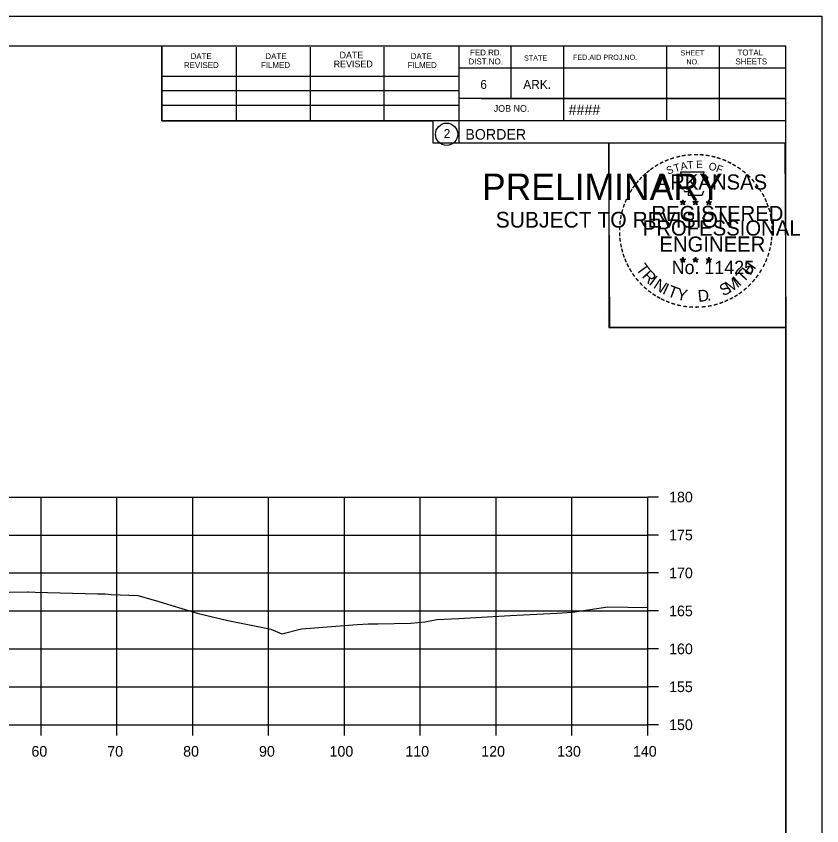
# Model space of a CAD drawing. Extents: x 1368503 to 1373085, y 379840 to 381833.
# Drawn here: x 1372978.8 to 1373085, y 381135 to 381241.7 of the extents above; entities that cross this region are included whole.
import ezdxf

# ---------------------------------------------------------------- set-up
doc = ezdxf.new("R2010")
doc.units = 0
for name, color, linetype in [('S_BRIDGE', 7, 'Continuous'), ('S_EDGE_PAVEMENT', 7, 'Continuous'), ('S_LANDSCAPING', 7, 'Continuous'), ('S_MISC_BOUNDARY', 7, 'Continuous'), ('S_MISC_BOUNDARY_ANNOT', 7, 'Continuous'), ('S_PHOTO_CENTERS', 7, 'Continuous'), ('S_PHOTO_NOTES', 7, 'Continuous'), ('S_TRAILS', 7, 'Continuous')]:
    doc.layers.add(name, color=color, linetype=linetype)

msp = doc.modelspace()

# ---------------------------------------------------------------- linework, layer by layer
at = {"layer": 'S_BRIDGE'}
for p, q in [((1372764.08, 381237.76), (1373080.26, 381237.76)), ((1372998, 381227.88), (1372998, 381237.76)), ((1373007.86, 381227.88), (1373007.86, 381237.56)), ((1373017.62, 381227.88), (1373017.62, 381237.56)), ((1373027.3, 381227.88), (1373027.3, 381237.56)), ((1373037.16, 381237.76), (1373037.16, 381224.96)), ((1373044, 381237.76), (1373044, 381230.82)), ((1373050.94, 381237.76), (1373050.94, 381227.88)), ((1373064.52, 381237.76), (1373064.52, 381227.88)), ((1373071.46, 381237.76), (1373071.46, 381227.88)), ((1373080.26, 381032.3), (1373080.26, 381237.76)), ((1373080.26, 381234.82), (1373037.16, 381234.82)), ((1373080.26, 381234.84), (1373080.26, 381234.84)), ((1372998, 381233.74), (1373037.16, 381233.74)), ((1372998, 381231.88), (1373037.16, 381231.88)), ((1373080.26, 381230.82), (1373037.16, 381230.82)), ((1373040.12, 381230.82), (1373080.26, 381230.82)), ((1372998, 381227.88), (1372998, 381229.94)), ((1372998, 381229.94), (1373037.16, 381229.94)), ((1373080.26, 381227.88), (1372998, 381227.88)), ((1373037.16, 381224.96), (1373080.26, 381224.96))]:
    msp.add_line(p, q, dxfattribs=at)
msp.add_circle((1373035.55, 381226.1), 1.47, dxfattribs=at)
at = {"layer": 'S_EDGE_PAVEMENT'}
for p, q in [((1373062.08, 381148.3), (1373062.08, 381178.3)), ((1373063.48, 381178.3), (1373062.08, 381178.3)), ((1373063.48, 381173.3), (1373062.08, 381173.3)), ((1373063.48, 381168.3), (1373062.08, 381168.3)), ((1373063.48, 381163.3), (1373062.08, 381163.3)), ((1373063.48, 381158.3), (1373062.08, 381158.3)), ((1373063.48, 381153.3), (1373062.08, 381153.3)), ((1372782.08, 381148.3), (1373062.08, 381148.3)), ((1372982.08, 381146.9), (1372982.08, 381148.3)), ((1372992.08, 381146.9), (1372992.08, 381148.3)), ((1373002.08, 381146.9), (1373002.08, 381148.3)), ((1373012.08, 381146.9), (1373012.08, 381148.3)), ((1373022.08, 381146.9), (1373022.08, 381148.3)), ((1373032.08, 381146.9), (1373032.08, 381148.3)), ((1373042.08, 381146.9), (1373042.08, 381148.3)), ((1373052.08, 381146.9), (1373052.08, 381148.3)), ((1373062.08, 381146.9), (1373062.08, 381148.3)), ((1373063.48, 381148.3), (1373062.08, 381148.3))]:
    msp.add_line(p, q, dxfattribs=at)
at = {"layer": 'S_LANDSCAPING'}
for p, q in [((1373066.7, 381217.47), (1373066.65, 381217.22)), ((1373066.7, 381217.11), (1373066.7, 381217.47)), ((1373066.7, 381217.47), (1373066.74, 381217.22)), ((1373068.37, 381217.47), (1373068.32, 381217.22)), ((1373068.37, 381217.11), (1373068.37, 381217.47)), ((1373068.37, 381217.47), (1373068.41, 381217.22)), ((1373070.13, 381217.46), (1373070.09, 381217.21)), ((1373070.13, 381217.09), (1373070.13, 381217.46)), ((1373070.13, 381217.46), (1373070.18, 381217.21)), ((1373066.35, 381217.22), (1373066.7, 381217.11)), ((1373066.35, 381217.22), (1373066.6, 381217.17)), ((1373066.35, 381217.22), (1373066.58, 381217.09)), ((1373066.48, 381216.81), (1373066.7, 381217.11)), ((1373066.48, 381216.81), (1373066.61, 381217.05)), ((1373066.48, 381216.81), (1373066.69, 381217.03)), ((1373066.91, 381216.81), (1373066.69, 381217.02)), ((1373067.04, 381217.22), (1373066.7, 381217.11)), ((1373066.91, 381216.81), (1373066.7, 381217.11)), ((1373067.04, 381217.22), (1373066.76, 381217.17)), ((1373066.91, 381216.81), (1373066.77, 381217.1)), ((1373067.04, 381217.22), (1373066.84, 381217.11)), ((1373068.02, 381217.22), (1373068.37, 381217.11)), ((1373068.02, 381217.22), (1373068.27, 381217.17)), ((1373068.02, 381217.22), (1373068.25, 381217.09)), ((1373068.15, 381216.81), (1373068.37, 381217.11)), ((1373068.15, 381216.81), (1373068.28, 381217.05)), ((1373068.15, 381216.81), (1373068.36, 381217.03)), ((1373068.58, 381216.81), (1373068.36, 381217.02)), ((1373068.71, 381217.22), (1373068.37, 381217.11)), ((1373068.58, 381216.81), (1373068.37, 381217.11)), ((1373068.71, 381217.22), (1373068.43, 381217.17)), ((1373068.58, 381216.81), (1373068.44, 381217.1)), ((1373068.71, 381217.22), (1373068.51, 381217.11)), ((1373069.78, 381217.2), (1373070.13, 381217.09)), ((1373069.78, 381217.2), (1373070.03, 381217.16)), ((1373069.78, 381217.2), (1373070.02, 381217.08)), ((1373069.91, 381216.8), (1373070.13, 381217.09)), ((1373069.91, 381216.8), (1373070.04, 381217.04)), ((1373069.91, 381216.8), (1373070.13, 381217.01)), ((1373070.48, 381217.2), (1373070.13, 381217.09)), ((1373070.34, 381216.8), (1373070.13, 381217.09)), ((1373070.34, 381216.8), (1373070.13, 381217.01)), ((1373070.48, 381217.2), (1373070.19, 381217.16)), ((1373070.34, 381216.8), (1373070.21, 381217.09)), ((1373070.48, 381217.2), (1373070.27, 381217.1)), ((1373066.69, 381209.9), (1373066.65, 381209.65)), ((1373066.69, 381209.53), (1373066.69, 381209.9)), ((1373066.69, 381209.9), (1373066.74, 381209.65)), ((1373068.36, 381209.9), (1373068.32, 381209.65)), ((1373068.36, 381209.53), (1373068.36, 381209.9)), ((1373068.36, 381209.9), (1373068.41, 381209.65)), ((1373070.13, 381209.89), (1373070.09, 381209.64)), ((1373070.13, 381209.52), (1373070.13, 381209.89)), ((1373070.13, 381209.89), (1373070.18, 381209.64)), ((1373066.34, 381209.64), (1373066.69, 381209.53)), ((1373066.34, 381209.64), (1373066.6, 381209.6)), ((1373066.34, 381209.64), (1373066.58, 381209.52)), ((1373066.48, 381209.24), (1373066.69, 381209.53)), ((1373066.48, 381209.24), (1373066.6, 381209.48)), ((1373066.48, 381209.24), (1373066.69, 381209.45)), ((1373067.04, 381209.64), (1373066.69, 381209.53)), ((1373066.9, 381209.24), (1373066.69, 381209.53)), ((1373066.9, 381209.24), (1373066.69, 381209.45)), ((1373067.04, 381209.64), (1373066.75, 381209.59)), ((1373066.9, 381209.24), (1373066.77, 381209.53)), ((1373067.04, 381209.64), (1373066.83, 381209.54)), ((1373068.01, 381209.64), (1373068.36, 381209.53)), ((1373068.01, 381209.64), (1373068.26, 381209.6)), ((1373068.01, 381209.64), (1373068.25, 381209.52)), ((1373068.14, 381209.24), (1373068.36, 381209.53)), ((1373068.14, 381209.24), (1373068.27, 381209.48)), ((1373068.14, 381209.24), (1373068.36, 381209.45)), ((1373068.71, 381209.64), (1373068.36, 381209.53)), ((1373068.57, 381209.24), (1373068.36, 381209.53)), ((1373068.57, 381209.24), (1373068.36, 381209.45)), ((1373068.71, 381209.64), (1373068.42, 381209.59)), ((1373068.57, 381209.24), (1373068.44, 381209.53)), ((1373068.71, 381209.64), (1373068.5, 381209.54)), ((1373069.78, 381209.63), (1373070.13, 381209.52)), ((1373069.78, 381209.63), (1373070.03, 381209.59)), ((1373069.78, 381209.63), (1373070.02, 381209.51)), ((1373069.91, 381209.23), (1373070.13, 381209.52)), ((1373069.91, 381209.23), (1373070.04, 381209.47)), ((1373069.91, 381209.23), (1373070.13, 381209.44)), ((1373070.47, 381209.63), (1373070.13, 381209.52)), ((1373070.34, 381209.23), (1373070.13, 381209.52)), ((1373070.34, 381209.23), (1373070.13, 381209.44)), ((1373070.47, 381209.63), (1373070.19, 381209.58)), ((1373070.34, 381209.23), (1373070.2, 381209.52)), ((1373070.47, 381209.63), (1373070.27, 381209.53))]:
    msp.add_line(p, q, dxfattribs=at)
for points in [[(1373066.39, 381221.09), (1373066.66, 381220.27)], [(1373069.9, 381220.17), (1373070.04, 381220.46), (1373069.36, 381220.43), (1373069.5, 381221.09), (1373066.39, 381221.09)], [(1373066.88, 381218.67), (1373066.88, 381218.58), (1373067.44, 381218.57), (1373067.39, 381218.09), (1373069.26, 381218.09), (1373069.46, 381218.63)], [(1373066.7, 381217.47), (1373066.91, 381216.81), (1373066.35, 381217.22), (1373067.04, 381217.22), (1373066.48, 381216.81), (1373066.7, 381217.47)], [(1373068.37, 381217.47), (1373068.58, 381216.81), (1373068.02, 381217.22), (1373068.71, 381217.22), (1373068.15, 381216.81), (1373068.37, 381217.47)], [(1373070.13, 381217.46), (1373070.34, 381216.8), (1373069.78, 381217.2), (1373070.48, 381217.2), (1373069.91, 381216.8), (1373070.13, 381217.46)], [(1373066.69, 381209.9), (1373066.9, 381209.24), (1373066.34, 381209.64), (1373067.04, 381209.64), (1373066.48, 381209.24), (1373066.69, 381209.9)], [(1373068.36, 381209.9), (1373068.57, 381209.24), (1373068.01, 381209.64), (1373068.71, 381209.64), (1373068.14, 381209.24), (1373068.36, 381209.9)], [(1373070.13, 381209.89), (1373070.34, 381209.23), (1373069.78, 381209.63), (1373070.47, 381209.63), (1373069.91, 381209.23), (1373070.13, 381209.89)]]:
    msp.add_lwpolyline(points, dxfattribs=at)
for centre, radius in [((1373066.69, 381217.1), 0.172), ((1373066.69, 381217.1), 0.145), ((1373068.36, 381217.1), 0.172), ((1373068.36, 381217.1), 0.145), ((1373070.13, 381217.09), 0.172), ((1373070.13, 381217.09), 0.145), ((1373066.69, 381217.1), 0.116), ((1373066.69, 381217.1), 0.0991), ((1373066.69, 381217.1), 0.0747), ((1373066.69, 381217.1), 0.0495), ((1373066.69, 381217.1), 0.0296), ((1373068.36, 381217.1), 0.116), ((1373068.36, 381217.1), 0.0991), ((1373068.36, 381217.1), 0.0747), ((1373068.36, 381217.1), 0.0495), ((1373068.36, 381217.1), 0.0296), ((1373070.13, 381217.09), 0.116), ((1373070.13, 381217.09), 0.0991), ((1373070.13, 381217.09), 0.0747), ((1373070.13, 381217.09), 0.0495), ((1373070.13, 381217.09), 0.0296), ((1373066.69, 381209.53), 0.172), ((1373066.69, 381209.53), 0.145), ((1373066.69, 381209.53), 0.116), ((1373066.69, 381209.53), 0.0991), ((1373066.69, 381209.53), 0.0747), ((1373066.69, 381209.53), 0.0495), ((1373066.69, 381209.53), 0.0296), ((1373068.36, 381209.53), 0.172), ((1373068.36, 381209.53), 0.145), ((1373068.36, 381209.53), 0.116), ((1373068.36, 381209.53), 0.0991), ((1373068.36, 381209.53), 0.0747), ((1373068.36, 381209.53), 0.0495), ((1373068.36, 381209.53), 0.0296), ((1373070.13, 381209.52), 0.172), ((1373070.13, 381209.52), 0.145), ((1373070.13, 381209.52), 0.116), ((1373070.13, 381209.52), 0.0991), ((1373070.13, 381209.52), 0.0747), ((1373070.13, 381209.52), 0.0495), ((1373070.13, 381209.52), 0.0296)]:
    msp.add_circle(centre, radius, dxfattribs=at)
at = {"layer": 'S_MISC_BOUNDARY'}
msp.add_lwpolyline([(1372970.68, 381165.65), (1372980.32, 381165.8), (1372980.43, 381165.8), (1372981.32, 381165.78), (1372989.52, 381165.57), (1372990.56, 381165.54), (1372991.33, 381165.48), (1372994.84, 381165.35), (1372997.19, 381164.66), (1373002.65, 381163.02), (1373006.7, 381162.05), (1373011.78, 381161.04), (1373012.4, 381160.89), (1373013.85, 381160.27), (1373016.44, 381160.96), (1373023.77, 381161.49), (1373025.23, 381161.58), (1373025.6, 381161.61), (1373026.48, 381161.59), (1373030.83, 381161.68), (1373032.66, 381161.85), (1373034.26, 381162.16), (1373037.16, 381162.32), (1373039.42, 381162.44), (1373043.95, 381162.71), (1373050.09, 381163.01), (1373052.13, 381163.12), (1373056.81, 381163.82), (1373062.08, 381163.77)], dxfattribs=at)
at = {"layer": 'S_PHOTO_CENTERS'}
for p, q in [((1372782.08, 381178.3), (1373062.08, 381178.3)), ((1372982.08, 381148.3), (1372982.08, 381178.3)), ((1372992.08, 381148.3), (1372992.08, 381178.3)), ((1373002.08, 381148.3), (1373002.08, 381178.3)), ((1373012.08, 381148.3), (1373012.08, 381178.3)), ((1373022.08, 381148.3), (1373022.08, 381178.3)), ((1373032.08, 381148.3), (1373032.08, 381178.3)), ((1373042.08, 381148.3), (1373042.08, 381178.3)), ((1373052.08, 381148.3), (1373052.08, 381178.3)), ((1373062.08, 381148.3), (1373062.08, 381178.3)), ((1372782.08, 381173.3), (1373062.08, 381173.3)), ((1372782.08, 381168.3), (1373062.08, 381168.3)), ((1372782.08, 381163.3), (1373062.08, 381163.3)), ((1372782.08, 381158.3), (1373062.08, 381158.3)), ((1372782.08, 381153.3), (1373062.08, 381153.3)), ((1372782.08, 381148.3), (1373062.08, 381148.3))]:
    msp.add_line(p, q, dxfattribs=at)
at = {"layer": 'S_PHOTO_NOTES'}
for p, q in [((1372751.68, 381241.66), (1373085.01, 381241.66)), ((1373056.3, 381202.51), (1373056.3, 381202.51))]:
    msp.add_line(p, q, dxfattribs=at)
for points in [[(1372751.67, 381241.66), (1373085.01, 381241.66), (1373085.01, 381028.32), (1372751.67, 381028.32)], [(1372998, 381237.76), (1372998, 381227.88), (1373033.73, 381227.88), (1373033.73, 381224.96), (1373056.93, 381224.96), (1373056.93, 381200.63), (1373080.26, 381200.63), (1373080.26, 381032.3), (1372764.08, 381032.3), (1372764.08, 381237.76)], [(1373056.93, 381224.96), (1373080.14, 381224.96), (1373080.26, 381200.63), (1373057.05, 381200.63)]]:
    msp.add_lwpolyline(points, close=True, dxfattribs=at)

# ---------------------------------------------------------------- texts
at = {"layer": 'S_BRIDGE'}
for s, height, p in [('DATE', 0.782, (1373001.8, 381236)), ('DATE', 0.782, (1373011.66, 381236)), ('DATE', 0.879, (1373021.44, 381236.1)), ('DATE', 0.782, (1373030.82, 381236)), ('FED.RD.', 0.782, (1373038.64, 381236.48)), ('STATE', 0.684, (1373045.76, 381235.8)), ('FED.AID PROJ.NO.', 0.684, (1373052.22, 381235.9)), ('SHEET', 0.684, (1373066.38, 381236.48)), ('TOTAL', 0.782, (1373073.9, 381236.48)), ('REVISED', 0.782, (1373000.92, 381234.82)), ('FILMED', 0.782, (1373011.08, 381234.82)), ('REVISED', 0.879, (1373020.66, 381234.92)), ('FILMED', 0.782, (1373030.42, 381234.82)), ('DIST.NO.', 0.782, (1373038.44, 381235.3)), ('NO.', 0.684, (1373067.16, 381235.3)), ('SHEETS', 0.782, (1373073.62, 381235.3)), ('6', 1.17, (1373040, 381232.08)), ('ARK.', 1.172, (1373045.66, 381232.08)), ('JOB NO.', 0.879, (1373041.76, 381229.06)), ('####', 1.4, (1373051.64, 381228.62)), ('2', 1.17, (1373035.17, 381225.61)), ('BORDER', 1.4, (1373038.02, 381225.39))]:
    msp.add_text(s, height=height, rotation=360, dxfattribs=at).set_placement(p)
at = {"layer": 'S_LANDSCAPING'}
for s, height, rotation, p in [('-', 1.6, 24.3072, (1373064.5, 381221.95)), ('-', 1.6, 19.1761, (1373065.14, 381222.22)), ('-', 1.6, 13.6301, (1373065.89, 381222.46)), ('-', 1.6, 10.2193, (1373066.56, 381222.62)), ('T', 1, 6.0228, (1373067.33, 381221.52)), ('-', 1.6, 5.8968, (1373067.29, 381222.73)), ('-', 1.6, 0.1862, (1373068.06, 381222.81)), ('E', 1, 0.8323, (1373068.44, 381221.63)), ('-', 1.6, 357.743, (1373068.79, 381222.79)), ('-', 1.6, 352.1617, (1373069.53, 381222.74)), ('-', 1.6, 347.2049, (1373070.25, 381222.62)), ('-', 1.6, 342.3362, (1373070.89, 381222.47)), ('-', 1.6, 337.8551, (1373071.62, 381222.25)), ('-', 1.6, 334.1211, (1373072.25, 381221.97)), ('-', 1.6, 36.2317, (1373062.69, 381220.87)), ('-', 1.6, 34.0636, (1373063.27, 381221.27)), ('-', 1.6, 28.7918, (1373063.87, 381221.64)), ('S', 1, 21.594, (1373064.74, 381220.77)), ('T', 1, 16.4036, (1373065.66, 381221.1)), ('A', 1, 11.2132, (1373066.48, 381221.35)), ('O', 1, 350.4515, (1373070.04, 381221.42)), ('F', 1, 340.0707, (1373070.99, 381221.19)), ('-', 1.6, 329.6409, (1373072.83, 381221.69)), ('-', 1.6, 325.8627, (1373073.47, 381221.33)), ('-', 1.6, 48.423, (1373061.34, 381219.6)), ('-', 1.6, 42.9622, (1373061.78, 381220.08)), ('-', 1.6, 38.9507, (1373062.22, 381220.49)), ('ARKANSAS', 2, 360, (1373063.24, 381218.81)), ('-', 1.6, 320.5297, (1373074.08, 381220.9)), ('-', 1.6, 315.5786, (1373074.68, 381220.42)), ('-', 1.6, 54.2325, (1373060.52, 381218.54)), ('-', 1.6, 50.6142, (1373060.93, 381219.11)), ('-', 1.6, 309.8797, (1373075.25, 381219.87)), ('-', 1.6, 306.6522, (1373075.78, 381219.26)), ('-', 1.6, 58.0706, (1373060.2, 381218.02)), ('-', 1.4, 303.6753, (1373076.26, 381218.7)), ('-', 1.6, 299.6684, (1373076.58, 381218.09)), ('-', 1.6, 67.7743, (1373059.62, 381216.79)), ('-', 1.6, 62.8713, (1373059.88, 381217.4)), ('-', 1.6, 294.6628, (1373076.91, 381217.48)), ('-', 1.6, 75.461, (1373059.21, 381215.45)), ('-', 1.6, 72.3945, (1373059.4, 381216.16)), ('REGISTERED', 2, 360, (1373062.56, 381214.66)), ('DWB', 0.01, 360, (1373066.68, 381217.1)), ('DWB', 0.01, 360, (1373068.35, 381217.1)), ('DWB', 0.01, 360, (1373070.12, 381217.09)), ('-', 1.6, 290.5728, (1373077.16, 381216.9)), ('-', 1.6, 285.1233, (1373077.4, 381216.32)), ('-', 1.6, 81.2013, (1373059.08, 381214.74)), ('-', 1.6, 280.5493, (1373077.6, 381215.58)), ('-', 1.6, 85.1863, (1373059, 381214.04)), ('PROFESSIONAL', 2, 360, (1373061.41, 381212.75)), ('-', 1.6, 276.5962, (1373077.76, 381214.81)), ('-', 1.6, 274.3301, (1373077.82, 381214.09)), ('-', 1.6, 94.1959, (1373059.01, 381212.62)), ('-', 1.6, 89.0622, (1373058.97, 381213.34)), ('-', 1.6, 269.9407, (1373077.85, 381213.46)), ('-', 1.6, 98.9479, (1373059.08, 381211.95)), ('ENGINEER', 2, 360, (1373063.6, 381210.63)), ('-', 1.6, 260.9953, (1373077.76, 381212.14)), ('-', 1.6, 263.5172, (1373077.83, 381212.79)), ('-', 1.6, 101.7149, (1373059.22, 381211.22)), ('-', 1.6, 105.4578, (1373059.38, 381210.62)), ('-', 1.6, 255.7626, (1373077.65, 381211.46)), ('-', 1.6, 109.0874, (1373059.59, 381209.99)), ('-', 1.6, 247.8887, (1373077.25, 381210.07)), ('-', 1.6, 252.8681, (1373077.47, 381210.74)), ('-', 1.6, 114.0643, (1373059.85, 381209.4)), ('-', 1.6, 115.7289, (1373060.15, 381208.78)), ('T', 1.54, 306.0406, (1373060.45, 381208.37)), ('No. 11425', 1.757, 360, (1373065.23, 381207.68)), ('DWB', 0.01, 360, (1373066.68, 381209.53)), ('DWB', 0.01, 360, (1373068.35, 381209.53)), ('DWB', 0.01, 360, (1373070.11, 381209.52)), ('H', 1.54, 54.6088, (1373075.57, 381207.41)), ('-', 1.6, 244.6197, (1373076.99, 381209.44)), ('-', 1.6, 120.4471, (1373060.51, 381208.19)), ('-', 1.6, 125.8934, (1373060.91, 381207.63)), ('R', 1.54, 314.005, (1373061.21, 381207.32)), ('T', 1.54, 46.6444, (1373074.68, 381206.46)), ('-', 1.6, 233.8452, (1373076.19, 381208.03)), ('-', 1.6, 239.0712, (1373076.59, 381208.68)), ('-', 1.6, 130.7181, (1373061.37, 381207.08)), ('-', 1.6, 134.2238, (1373061.89, 381206.53)), ('I', 1.54, 321.9694, (1373062.11, 381206.39)), ('N', 1.54, 326.5002, (1373062.68, 381205.92)), ('M', 1.54, 32.6563, (1373072.84, 381205.14)), ('I', 1.54, 42.1136, (1373074.12, 381205.99)), ('-', 1.6, 231.2538, (1373075.76, 381207.47)), ('-', 1.6, 138.9338, (1373062.42, 381206.07)), ('-', 1.6, 144.6463, (1373062.97, 381205.66)), ('I', 1.54, 335.3603, (1373063.89, 381205.13)), ('T', 1.54, 339.8912, (1373064.55, 381204.81)), ('Y', 1.54, 347.8556, (1373065.77, 381204.36)), ('D', 1.54, 6.3969, (1373068.75, 381204)), ('S', 1.54, 26.9312, (1373072, 381204.73)), ('-', 1.6, 221.0851, (1373074.76, 381206.39)), ('-', 1.6, 225.7653, (1373075.28, 381206.9)), ('-', 1.6, 148.0898, (1373063.53, 381205.29)), ('-', 1.6, 151.5704, (1373064.11, 381204.97)), ('-', 1.6, 154.6002, (1373064.63, 381204.72)), ('.', 1.54, 13.7642, (1373069.94, 381204.13)), ('-', 1.6, 207.3568, (1373073.12, 381205.19)), ('-', 1.6, 212.2491, (1373073.68, 381205.53)), ('-', 1.6, 215.7363, (1373074.21, 381205.92)), ('-', 1.6, 158.5612, (1373065.26, 381204.47)), ('-', 1.6, 162.7983, (1373065.95, 381204.25)), ('-', 1.6, 167.5555, (1373066.66, 381204.09)), ('-', 1.6, 173.1155, (1373067.43, 381203.98)), ('-', 1.6, 176.5183, (1373068.18, 381203.93)), ('-', 1.6, 181.5918, (1373068.92, 381203.95)), ('-', 1.6, 185.8167, (1373069.73, 381204.02)), ('-', 1.6, 191.2858, (1373070.47, 381204.15)), ('-', 1.6, 195.4743, (1373071.2, 381204.35)), ('-', 1.6, 200.7184, (1373071.88, 381204.6)), ('-', 1.6, 204.2516, (1373072.49, 381204.87))]:
    msp.add_text(s, height=height, rotation=rotation, dxfattribs=at).set_placement(p)
at = {"layer": 'S_MISC_BOUNDARY_ANNOT'}
for s, height, p in [('PRELIMINARY', 3.5, (1373040.21, 381217.42)), ('DWB', 0.01, (1373040.96, 381219.27)), ('SUBJECT TO REVISION', 2.0751, (1373042.02, 381213.8))]:
    msp.add_text(s, height=height, rotation=360, dxfattribs=at).set_placement(p)
at = {"layer": 'S_TRAILS'}
for s, p in [('180', (1373064.88, 381177.6)), ('175', (1373064.88, 381172.6)), ('170', (1373064.88, 381167.6)), ('165', (1373064.88, 381162.6)), ('160', (1373064.88, 381157.6)), ('155', (1373064.88, 381152.6)), ('150', (1373064.88, 381147.6)), ('60', (1372980.82, 381144.1)), ('70', (1372990.82, 381144.1)), ('80', (1373000.82, 381144.1)), ('90', (1373010.82, 381144.1)), ('100', (1373020.12, 381144.1)), ('110', (1373030.12, 381144.1)), ('120', (1373040.12, 381144.1)), ('130', (1373050.12, 381144.1)), ('140', (1373060.12, 381144.1))]:
    msp.add_text(s, height=1.4, dxfattribs=at).set_placement(p)

doc.saveas('drawing.dxf')
